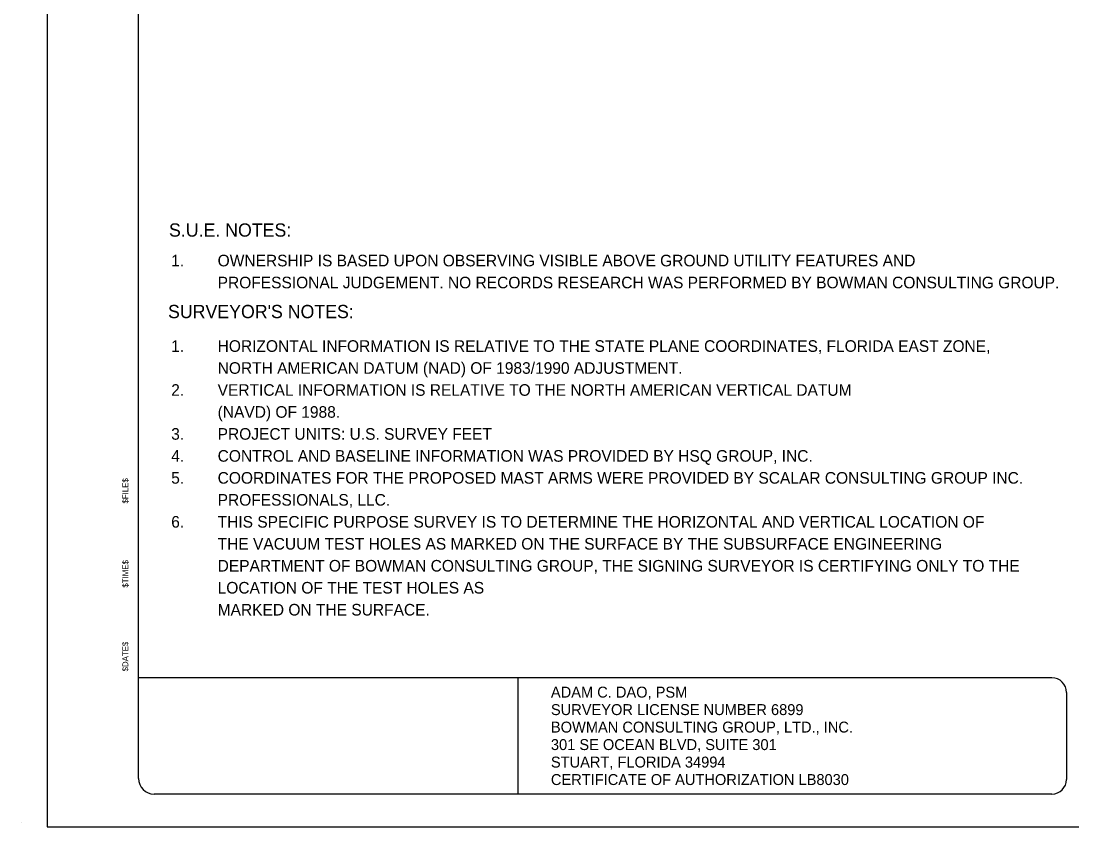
# Model space of a CAD drawing. Extents: x -769.4 to -731.2, y -2181.6 to -2171.
# Drawn here: x -749.29 to -742.95, y -2181.58 to -2176.72 of the extents above; entities that cross this region are included whole.
import ezdxf

# ---------------------------------------------------------------- set-up
doc = ezdxf.new("R2010")
doc.units = 0
for name, color, linetype in [('AdhocPoint_dp', 7, 'Continuous'), ('Default', 7, 'Continuous'), ('PlotBorder_dp', 7, 'Continuous'), ('TextNotes', 7, 'Continuous'), ('TextSurveyLabel', 7, 'Continuous')]:
    doc.layers.add(name, color=color, linetype=linetype)

msp = doc.modelspace()

# ---------------------------------------------------------------- linework, layer by layer
at = {"layer": 'AdhocPoint_dp'}
msp.add_line((-749.292, -2181.5516), (-749.292, -2181.5516), dxfattribs=at)
at = {"layer": 'Default'}
for p, q in [((-748.5834, -2181.2893), (-748.5834, -2171.1752)), ((-743.0756, -2180.6815), (-748.5834, -2180.6815)), ((-746.2947, -2181.3829), (-746.2947, -2180.6815)), ((-742.9874, -2180.7697), (-742.9874, -2181.2946)), ((-743.0756, -2181.3828), (-748.4899, -2181.3828))]:
    msp.add_line(p, q, dxfattribs=at)
for centre, major_axis, start_param, end_param in [((-743.0756, -2180.7697), (0, 0.0882), 4.712389, 6.283185), ((-748.4898, -2181.2893), (0, -0.0935), 4.712389, 6.283185), ((-743.0756, -2181.2946), (0, 0.0882), 3.141593, 4.712389)]:
    msp.add_ellipse(centre, major_axis=major_axis, ratio=0.999927, start_param=start_param, end_param=end_param, dxfattribs=at)
at = {"layer": 'PlotBorder_dp'}
msp.add_lwpolyline([(-749.1334, -2181.5815), (-732.6334, -2181.5815), (-732.6334, -2170.9815), (-749.1334, -2170.9815)], close=True, dxfattribs=at)

# ---------------------------------------------------------------- texts
at = {"layer": 'Default'}
for s, p in [('$FILE$', (-748.6453, -2179.6311)), ('$TIME$', (-748.6448, -2180.1381)), ('$DATE$', (-748.6454, -2180.6432))]:
    msp.add_text(s, height=0.03542, rotation=90, dxfattribs=at).set_placement(p)
at = {"layer": 'TextNotes'}
for s, p in [('ADAM C. DAO, PSM', (-746.0965, -2180.8013)), ('SURVEYOR LICENSE NUMBER 6899', (-746.0965, -2180.9067)), ('BOWMAN CONSULTING GROUP, LTD., INC.', (-746.0965, -2181.0121)), ('301 SE OCEAN BLVD, SUITE 301          ', (-746.0965, -2181.1176)), ('STUART, FLORIDA 34994                 ', (-746.0965, -2181.223)), ('CERTIFICATE OF AUTHORIZATION LB8030', (-746.0965, -2181.3285))]:
    msp.add_text(s, height=0.065904, rotation=360, dxfattribs=at).set_placement(p)
at = {"layer": 'TextSurveyLabel'}
for s, height, p in [('S.U.E. NOTES:', 0.08, (-748.3997, -2178.0217)), ('1.', 0.07, (-748.3863, -2178.2008)), ('OWNERSHIP IS BASED UPON OBSERVING VISIBLE ABOVE GROUND UTILITY FEATURES AND ', 0.07, (-748.1063, -2178.2008)), ('PROFESSIONAL JUDGEMENT. NO RECORDS RESEARCH WAS PERFORMED BY BOWMAN CONSULTING GROUP.', 0.07, (-748.1063, -2178.3333)), ("SURVEYOR'S NOTES:", 0.08, (-748.4055, -2178.5132)), ('1.', 0.07, (-748.3863, -2178.7163)), ('HORIZONTAL INFORMATION IS RELATIVE TO THE STATE PLANE COORDINATES, FLORIDA EAST ZONE, ', 0.07, (-748.1063, -2178.7163)), ('NORTH AMERICAN DATUM (NAD) OF 1983/1990 ADJUSTMENT.', 0.07, (-748.1063, -2178.8488)), ('2.', 0.07, (-748.3863, -2178.9813)), ('VERTICAL INFORMATION IS RELATIVE TO THE NORTH AMERICAN VERTICAL DATUM', 0.07, (-748.1063, -2178.9813)), ('(NAVD) OF 1988.', 0.07, (-748.1063, -2179.1138)), ('3.', 0.07, (-748.3863, -2179.2463)), ('PROJECT UNITS: U.S. SURVEY FEET', 0.07, (-748.1063, -2179.2463)), ('4.', 0.07, (-748.3863, -2179.3788)), ('CONTROL AND BASELINE INFORMATION WAS PROVIDED BY HSQ GROUP, INC.', 0.07, (-748.1063, -2179.3788)), ('5.', 0.07, (-748.3863, -2179.5113)), ('COORDINATES FOR THE PROPOSED MAST ARMS WERE PROVIDED BY SCALAR CONSULTING GROUP INC. ', 0.07, (-748.1063, -2179.5113)), ('PROFESSIONALS, LLC.', 0.07, (-748.1063, -2179.6438)), ('6.', 0.07, (-748.3863, -2179.7763)), ('THIS SPECIFIC PURPOSE SURVEY IS TO DETERMINE THE HORIZONTAL AND VERTICAL LOCATION OF ', 0.07, (-748.1063, -2179.7763)), ('THE VACUUM TEST HOLES AS MARKED ON THE SURFACE BY THE SUBSURFACE ENGINEERING ', 0.07, (-748.1063, -2179.9088)), ('DEPARTMENT OF BOWMAN CONSULTING GROUP, THE SIGNING SURVEYOR IS CERTIFYING ONLY TO THE ', 0.07, (-748.1063, -2180.0413)), ('LOCATION OF THE TEST HOLES AS ', 0.07, (-748.1063, -2180.1738)), ('MARKED ON THE SURFACE.  ', 0.07, (-748.1063, -2180.3063))]:
    msp.add_text(s, height=height, rotation=360, dxfattribs=at).set_placement(p)

doc.saveas('drawing.dxf')
